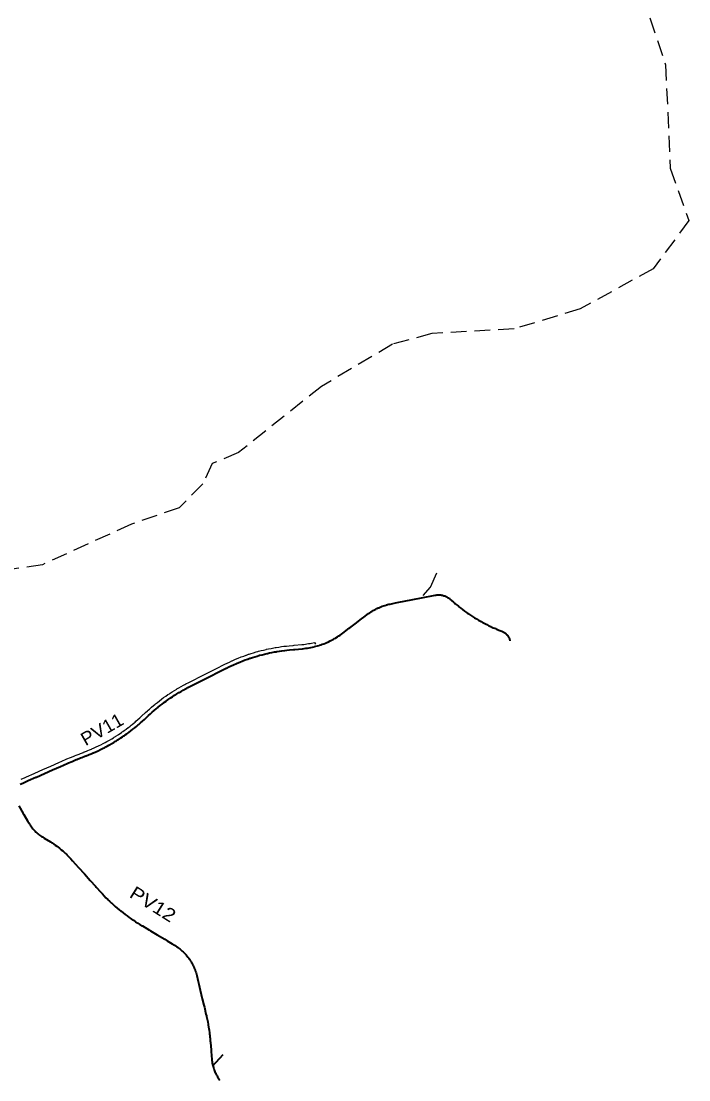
# Model space of a CAD drawing. Extents: x -509392 to -507242, y -1124532 to -1120864.
# Drawn here: x -508000 to -507242, y -1123169 to -1121966 of the extents above; entities that cross this region are included whole.
import ezdxf
from ezdxf.enums import TextEntityAlignment as Align

# ---------------------------------------------------------------- set-up
doc = ezdxf.new("R2010")
doc.units = 0
doc.header["$LTSCALE"] = 6
doc.linetypes.add('DOT_DASHED', pattern=[7.7, 5, -1.2, 0.3, -1.2])
doc.linetypes.add('MEDIUM_DASHED', pattern=[4.5, 3, -1.5])
for name, color, linetype, lineweight in [('1', 7, 'DOT_DASHED', 25), ('15', 7, 'Continuous', 35), ('3', 7, 'MEDIUM_DASHED', 25)]:
    doc.layers.add(name, color=color, linetype=linetype, lineweight=lineweight)

msp = doc.modelspace()

# ---------------------------------------------------------------- linework, layer by layer
at = {"layer": '1'}
for points in [[(-507856.144, -1122748.853), (-507854.55, -1122747.419), (-507852.329, -1122745.473), (-507850.08, -1122743.557), (-507848.408, -1122742.17), (-507847.798, -1122741.67), (-507845.497, -1122739.822), (-507843.165, -1122738.006), (-507840.813, -1122736.226), (-507840.332, -1122735.869), (-507838.425, -1122734.472), (-507836.018, -1122732.759), (-507833.588, -1122731.08), (-507831.962, -1122729.987), (-507831.127, -1122729.433), (-507828.651, -1122727.826), (-507826.149, -1122726.254), (-507823.629, -1122724.722), (-507823.297, -1122724.523), (-507821.077, -1122723.218), (-507818.509, -1122721.755), (-507815.922, -1122720.331), (-507814.381, -1122719.506), (-507813.312, -1122718.942), (-507812.782, -1122718.667), (-507812.454, -1122718.496), (-507810.686, -1122717.594), (-507805.385, -1122714.919), (-507796.457, -1122710.415), (-507787.529, -1122705.911), (-507778.601, -1122701.407), (-507769.672, -1122696.902), (-507769.044, -1122696.586), (-507766.414, -1122695.283), (-507763.758, -1122694.014), (-507761.089, -1122692.786), (-507760.447, -1122692.497), (-507758.394, -1122691.592), (-507756.813, -1122690.912), (-507755.681, -1122690.437), (-507752.963, -1122689.325), (-507751.008, -1122688.554), (-507750.216, -1122688.248), (-507747.465, -1122687.214), (-507744.701, -1122686.221), (-507744.461, -1122686.137), (-507741.916, -1122685.264), (-507741.369, -1122685.082), (-507739.113, -1122684.347), (-507736.304, -1122683.472), (-507733.484, -1122682.639), (-507731.585, -1122682.102), (-507730.644, -1122681.842), (-507727.802, -1122681.09), (-507724.947, -1122680.378), (-507722.088, -1122679.709), (-507721.649, -1122679.61), (-507719.205, -1122679.077), (-507716.322, -1122678.489), (-507713.432, -1122677.942), (-507711.614, -1122677.62), (-507710.526, -1122677.436), (-507707.624, -1122676.973), (-507704.71, -1122676.551), (-507701.806, -1122676.173)], [(-507701.789, -1122676.171), (-507701.477, -1122676.133), (-507698.867, -1122675.833), (-507695.947, -1122675.538), (-507691.407, -1122675.113), (-507690.016, -1122674.982), (-507681.451, -1122674.179), (-507681.066, -1122674.143), (-507679.254, -1122673.954), (-507677.456, -1122673.727), (-507675.664, -1122673.463), (-507673.878, -1122673.16), (-507672.096, -1122672.819), (-507672.079, -1122672.815), (-507670.328, -1122672.442), (-507667.071, -1122671.673), (-507665.943, -1122673.704)], [(-508000.267, -1122827.114), (-507995.799, -1122825.113), (-507994.074, -1122824.35), (-507985.697, -1122820.648), (-507984.928, -1122820.308), (-507975.78, -1122816.265), (-507966.634, -1122812.223), (-507957.487, -1122808.18), (-507954.038, -1122806.656), (-507949.198, -1122804.547), (-507948.269, -1122804.149), (-507944.323, -1122802.483), (-507939.437, -1122800.475), (-507938.945, -1122800.276), (-507934.523, -1122798.515), (-507933.03, -1122797.931), (-507929.589, -1122796.606), (-507929.549, -1122796.591), (-507928.434, -1122796.167), (-507928.019, -1122796.009), (-507925.363, -1122794.975), (-507924.69, -1122794.707), (-507922.741, -1122793.911), (-507920.449, -1122792.944), (-507920.133, -1122792.808), (-507917.531, -1122791.663), (-507914.952, -1122790.482), (-507912.385, -1122789.263), (-507911.585, -1122788.873), (-507909.847, -1122788.012), (-507907.316, -1122786.717), (-507906.364, -1122786.218), (-507904.814, -1122785.391), (-507902.923, -1122784.358), (-507902.332, -1122784.029), (-507899.86, -1122782.626), (-507897.413, -1122781.19), (-507895.497, -1122780.032), (-507894.989, -1122779.719), (-507894.509, -1122779.422), (-507892.956, -1122778.448), (-507892.591, -1122778.216), (-507890.199, -1122776.668), (-507889.58, -1122776.259), (-507887.845, -1122775.095), (-507886.344, -1122774.065), (-507885.509, -1122773.485), (-507884.746, -1122772.949), (-507883.2, -1122771.844), (-507880.91, -1122770.165), (-507878.642, -1122768.451), (-507878.465, -1122768.315), (-507876.407, -1122766.71), (-507875.291, -1122765.823), (-507874.199, -1122764.94), (-507872.008, -1122763.129), (-507870.874, -1122762.169), (-507869.852, -1122761.294), (-507867.716, -1122759.422), (-507865.606, -1122757.516), (-507863.541, -1122755.625), (-507858.982, -1122751.45), (-507858.951, -1122751.421), (-507856.743, -1122749.4), (-507856.153, -1122748.862)]]:
    msp.add_lwpolyline(points, dxfattribs=at)
at = {"layer": '15'}
msp.add_line((-507782.865, -1123153.213), (-507770.728, -1123139.816), dxfattribs=at)
for points in [[(-507585.778, -1122629.265), (-507584.798, -1122628.997), (-507584.242, -1122628.854), (-507582.695, -1122628.483), (-507581.139, -1122628.154), (-507575.013, -1122626.942), (-507571.329, -1122626.213), (-507565.204, -1122625.002), (-507555.394, -1122623.061), (-507545.584, -1122621.121), (-507539.977, -1122620.012), (-507535.774, -1122619.18), (-507533.733, -1122618.776), (-507530.167, -1122618.071), (-507529.251, -1122617.912), (-507528.329, -1122617.796), (-507527.402, -1122617.722), (-507526.473, -1122617.692), (-507525.907, -1122617.695), (-507525.544, -1122617.705), (-507524.616, -1122617.761), (-507524.374, -1122617.782), (-507523.691, -1122617.86), (-507522.773, -1122618.002), (-507521.862, -1122618.186), (-507520.96, -1122618.413), (-507520.07, -1122618.681), (-507519.194, -1122618.991), (-507518.332, -1122619.34), (-507517.488, -1122619.73), (-507516.663, -1122620.158), (-507516.367, -1122620.324), (-507515.859, -1122620.624), (-507515.077, -1122621.127), (-507514.32, -1122621.666), (-507513.588, -1122622.239), (-507512.884, -1122622.846), (-507511.688, -1122623.925), (-507511.332, -1122624.247), (-507509.316, -1122626.039), (-507508.635, -1122626.633), (-507508.23, -1122626.983), (-507507.274, -1122627.801), (-507505.205, -1122629.533), (-507503.721, -1122630.743), (-507503.111, -1122631.233), (-507500.992, -1122632.902), (-507500.902, -1122632.971), (-507498.847, -1122634.538), (-507496.679, -1122636.142), (-507494.487, -1122637.714), (-507492.829, -1122638.87), (-507492.271, -1122639.253), (-507490.033, -1122640.758), (-507487.772, -1122642.229), (-507485.489, -1122643.667), (-507484.441, -1122644.312), (-507483.186, -1122645.07), (-507480.861, -1122646.438), (-507478.516, -1122647.772), (-507477.876, -1122648.128), (-507476.152, -1122649.07), (-507475.763, -1122649.279), (-507473.768, -1122650.333), (-507471.366, -1122651.559)], [(-507701.213, -1122680.886), (-507700.912, -1122680.849), (-507698.357, -1122680.556), (-507695.496, -1122680.267), (-507690.964, -1122679.842), (-507689.573, -1122679.711), (-507681.007, -1122678.908), (-507680.612, -1122678.871), (-507678.71, -1122678.673), (-507676.812, -1122678.433), (-507674.92, -1122678.154), (-507673.035, -1122677.835), (-507671.157, -1122677.475), (-507671.117, -1122677.467), (-507669.286, -1122677.076), (-507667.425, -1122676.637), (-507667.216, -1122676.585), (-507665.573, -1122676.158), (-507663.732, -1122675.641), (-507661.903, -1122675.084), (-507661.447, -1122674.939), (-507660.085, -1122674.489), (-507658.281, -1122673.855), (-507656.491, -1122673.183), (-507654.715, -1122672.473), (-507652.955, -1122671.725), (-507652.117, -1122671.354), (-507651.211, -1122670.94), (-507649.484, -1122670.119), (-507647.775, -1122669.261), (-507646.084, -1122668.366), (-507645.681, -1122668.146), (-507644.413, -1122667.436), (-507643.242, -1122666.757), (-507642.762, -1122666.471), (-507641.132, -1122665.471), (-507639.524, -1122664.436), (-507637.938, -1122663.368), (-507636.375, -1122662.266), (-507634.932, -1122661.204), (-507634.836, -1122661.131), (-507627.649, -1122655.713), (-507626.947, -1122655.184), (-507619.447, -1122649.53), (-507618.962, -1122649.164), (-507613.599, -1122645.122), (-507610.976, -1122643.145), (-507605.614, -1122639.102), (-507604.331, -1122638.162), (-507603.024, -1122637.255), (-507602.938, -1122637.198), (-507601.693, -1122636.384), (-507600.34, -1122635.548), (-507598.965, -1122634.749), (-507597.569, -1122633.986), (-507596.154, -1122633.261), (-507594.72, -1122632.573), (-507594.211, -1122632.34), (-507593.268, -1122631.923), (-507591.799, -1122631.313), (-507590.315, -1122630.741), (-507588.816, -1122630.209), (-507587.303, -1122629.717), (-507586.14, -1122629.368), (-507585.778, -1122629.265)], [(-507471.366, -1122651.559), (-507468.945, -1122652.75), (-507466.823, -1122653.757), (-507466.507, -1122653.904), (-507464.052, -1122655.022), (-507462.37, -1122655.762), (-507461.58, -1122656.102), (-507460.262, -1122656.661), (-507459.093, -1122657.146), (-507457.648, -1122657.732), (-507456.59, -1122658.152), (-507454.322, -1122659.044), (-507453.594, -1122659.352), (-507452.884, -1122659.699), (-507452.192, -1122660.082), (-507451.522, -1122660.502), (-507450.875, -1122660.956), (-507450.253, -1122661.444), (-507449.657, -1122661.963), (-507449.089, -1122662.514), (-507449.02, -1122662.585), (-507448.551, -1122663.093), (-507448.045, -1122663.701), (-507447.571, -1122664.334), (-507447.131, -1122664.991), (-507446.727, -1122665.67), (-507446.359, -1122666.37), (-507446.157, -1122666.795), (-507446.028, -1122667.088), (-507445.753, -1122667.773), (-507445.735, -1122667.822), (-507445.482, -1122668.571), (-507445.268, -1122669.332), (-507445.14, -1122669.84)], [(-507852.957, -1122752.376), (-507851.394, -1122750.97), (-507849.223, -1122749.067), (-507847.025, -1122747.195), (-507845.391, -1122745.838), (-507844.8, -1122745.355), (-507842.549, -1122743.548), (-507840.272, -1122741.773), (-507837.97, -1122740.031), (-507837.508, -1122739.687), (-507835.643, -1122738.323), (-507833.291, -1122736.648), (-507830.916, -1122735.007), (-507829.327, -1122733.938), (-507828.517, -1122733.401), (-507826.095, -1122731.83), (-507823.65, -1122730.294), (-507821.184, -1122728.793), (-507820.869, -1122728.605), (-507818.696, -1122727.328), (-507816.188, -1122725.9), (-507813.659, -1122724.507), (-507812.155, -1122723.701), (-507811.11, -1122723.151), (-507810.592, -1122722.882), (-507810.275, -1122722.717), (-507808.542, -1122721.832), (-507803.246, -1122719.16), (-507794.318, -1122714.656), (-507785.389, -1122710.152), (-507776.461, -1122705.648), (-507767.533, -1122701.144), (-507766.912, -1122700.83), (-507764.335, -1122699.554), (-507761.741, -1122698.314), (-507759.13, -1122697.112), (-507758.51, -1122696.834), (-507756.501, -1122695.948), (-507754.955, -1122695.285), (-507753.856, -1122694.822), (-507751.194, -1122693.734), (-507749.284, -1122692.98), (-507748.518, -1122692.684), (-507745.827, -1122691.673), (-507743.121, -1122690.7), (-507742.899, -1122690.622), (-507740.402, -1122689.767), (-507739.877, -1122689.592), (-507737.669, -1122688.872), (-507734.924, -1122688.018), (-507732.168, -1122687.202), (-507730.312, -1122686.678), (-507729.399, -1122686.427), (-507726.62, -1122685.691), (-507723.83, -1122684.995), (-507721.031, -1122684.34), (-507720.613, -1122684.245), (-507718.223, -1122683.724), (-507715.406, -1122683.149), (-507712.581, -1122682.615), (-507710.805, -1122682.301), (-507709.748, -1122682.122), (-507706.909, -1122681.669), (-507704.064, -1122681.257), (-507701.213, -1122680.886)], [(-507998.313, -1122831.443), (-507993.874, -1122829.455), (-507992.153, -1122828.695), (-507983.776, -1122824.992), (-507983.007, -1122824.652), (-507973.86, -1122820.61), (-507964.714, -1122816.567), (-507955.568, -1122812.525), (-507952.123, -1122811.002), (-507947.32, -1122808.909), (-507946.405, -1122808.518), (-507942.495, -1122806.867), (-507937.65, -1122804.876), (-507937.171, -1122804.682), (-507932.784, -1122802.935), (-507931.31, -1122802.359), (-507927.898, -1122801.045), (-507927.861, -1122801.031), (-507926.744, -1122800.606), (-507926.321, -1122800.445), (-507923.613, -1122799.392), (-507922.916, -1122799.113), (-507920.921, -1122798.299), (-507918.58, -1122797.311), (-507918.245, -1122797.167), (-507915.586, -1122795.997), (-507912.944, -1122794.788), (-507910.319, -1122793.54), (-507909.493, -1122793.138), (-507907.714, -1122792.255), (-507905.127, -1122790.932), (-507904.145, -1122790.418), (-507902.559, -1122789.572), (-507900.627, -1122788.516), (-507900.012, -1122788.174), (-507897.485, -1122786.74), (-507894.979, -1122785.269), (-507893.019, -1122784.084), (-507892.495, -1122783.762), (-507892.002, -1122783.457), (-507890.416, -1122782.462), (-507890.033, -1122782.219), (-507887.594, -1122780.64), (-507886.953, -1122780.216), (-507885.178, -1122779.026), (-507883.641, -1122777.972), (-507882.786, -1122777.377), (-507882.003, -1122776.826), (-507880.418, -1122775.693), (-507878.074, -1122773.976), (-507875.756, -1122772.224), (-507875.565, -1122772.077), (-507873.463, -1122770.439), (-507872.319, -1122769.528), (-507871.197, -1122768.621), (-507868.957, -1122766.77), (-507867.793, -1122765.786), (-507866.745, -1122764.886), (-507864.56, -1122762.971), (-507862.403, -1122761.024), (-507860.333, -1122759.128), (-507855.766, -1122754.946), (-507855.734, -1122754.917), (-507853.537, -1122752.904), (-507852.957, -1122752.376)], [(-508001.273, -1122832.797), (-507998.313, -1122831.443)], [(-508002.892, -1122857.242), (-507997.895, -1122865.904), (-507997.186, -1122867.133), (-507992.898, -1122874.567), (-507992.519, -1122875.225), (-507991.583, -1122876.847), (-507990.892, -1122878.006), (-507990.186, -1122879.113), (-507989.449, -1122880.2), (-507988.681, -1122881.263), (-507987.868, -1122882.322), (-507987.052, -1122883.323), (-507986.193, -1122884.316), (-507985.304, -1122885.285), (-507984.389, -1122886.228), (-507983.447, -1122887.142), (-507982.476, -1122888.031), (-507981.589, -1122888.798), (-507981.51, -1122888.864), (-507980.465, -1122889.715), (-507979.423, -1122890.513), (-507978.358, -1122891.28), (-507977.271, -1122892.016), (-507976.132, -1122892.74), (-507974.011, -1122894.045), (-507966.909, -1122898.413), (-507966.748, -1122898.513), (-507966.549, -1122898.637), (-507965.442, -1122899.334), (-507965.083, -1122899.563), (-507963.303, -1122900.735), (-507961.535, -1122901.952), (-507959.79, -1122903.205), (-507958.077, -1122904.49), (-507956.884, -1122905.418), (-507956.366, -1122905.83), (-507954.716, -1122907.176), (-507953.079, -1122908.569), (-507951.472, -1122909.993), (-507949.902, -1122911.443), (-507948.976, -1122912.327), (-507948.336, -1122912.951), (-507946.829, -1122914.461), (-507945.357, -1122916), (-507944.93, -1122916.458), (-507943.903, -1122917.582), (-507941.864, -1122919.847), (-507935.174, -1122927.279), (-507928.485, -1122934.711), (-507921.794, -1122942.143), (-507915.899, -1122948.692), (-507915.104, -1122949.575), (-507909.886, -1122955.372), (-507908.436, -1122956.966), (-507907.937, -1122957.505), (-507905.946, -1122959.621), (-507903.934, -1122961.696), (-507901.881, -1122963.752), (-507901.674, -1122963.955), (-507899.819, -1122965.756), (-507897.688, -1122967.765)], [(-507897.741, -1122967.716), (-507895.575, -1122969.7), (-507894.543, -1122970.625), (-507893.43, -1122971.608), (-507891.232, -1122973.503), (-507889.014, -1122975.361), (-507887.091, -1122976.926), (-507886.786, -1122977.17), (-507884.501, -1122978.972), (-507882.205, -1122980.727), (-507879.872, -1122982.456), (-507879.357, -1122982.829), (-507877.528, -1122984.139), (-507876.604, -1122984.788), (-507875.167, -1122985.783), (-507872.758, -1122987.406), (-507871.309, -1122988.359), (-507870.352, -1122988.978), (-507867.899, -1122990.528), (-507865.417, -1122992.046), (-507862.963, -1122993.521), (-507862.498, -1122993.8), (-507857.72, -1122996.674), (-507854.389, -1122998.676), (-507853.211, -1122999.385), (-507845.82, -1123003.828), (-507837.249, -1123008.982), (-507834.562, -1123010.599), (-507828.68, -1123014.136), (-507825.963, -1123015.769), (-507824.667, -1123016.574), (-507823.365, -1123017.434), (-507822.088, -1123018.331), (-507820.841, -1123019.26), (-507819.829, -1123020.057), (-507819.591, -1123020.25), (-507818.426, -1123021.226), (-507817.621, -1123021.934), (-507817.231, -1123022.286), (-507816.112, -1123023.338), (-507815.006, -1123024.438), (-507813.931, -1123025.57), (-507812.892, -1123026.728), (-507812.013, -1123027.761), (-507811.863, -1123027.941), (-507810.905, -1123029.139), (-507809.965, -1123030.385), (-507809.062, -1123031.656), (-507808.194, -1123032.953), (-507807.364, -1123034.273), (-507806.637, -1123035.503), (-507806.568, -1123035.622), (-507805.868, -1123036.887), (-507805.793, -1123037.029), (-507805.101, -1123038.37), (-507804.425, -1123039.776), (-507803.789, -1123041.203), (-507803.195, -1123042.644), (-507802.641, -1123044.102), (-507802.129, -1123045.577), (-507801.66, -1123047.063), (-507801.636, -1123047.149), (-507801.232, -1123048.565), (-507800.855, -1123050.044), (-507799.183, -1123057.026)], [(-507799.183, -1123057.028), (-507798.858, -1123058.385), (-507798.518, -1123059.802), (-507796.854, -1123066.751), (-507794.526, -1123076.476), (-507792.745, -1123083.911), (-507792.197, -1123086.201), (-507790.374, -1123093.813), (-507789.869, -1123095.975), (-507789.678, -1123096.823), (-507789.029, -1123099.829), (-507788.423, -1123102.859), (-507787.868, -1123105.872), (-507787.839, -1123106.037), (-507787.351, -1123108.934), (-507787.115, -1123110.433), (-507786.879, -1123112.006), (-507786.46, -1123115.047), (-507786.317, -1123116.169), (-507786.082, -1123118.127), (-507785.811, -1123120.625), (-507785.752, -1123121.213), (-507785.471, -1123124.254), (-507785.297, -1123126.311), (-507784.614, -1123134.388), (-507784.455, -1123136.276), (-507783.669, -1123145.579), (-507783.615, -1123146.17), (-507783.538, -1123146.903), (-507783.45, -1123147.62), (-507783.373, -1123148.184), (-507783.164, -1123149.497), (-507782.921, -1123150.789), (-507782.641, -1123152.07), (-507782.323, -1123153.342), (-507781.962, -1123154.628), (-507781.858, -1123154.972), (-507781.581, -1123155.846), (-507781.15, -1123157.097), (-507780.686, -1123158.323), (-507780.187, -1123159.536), (-507779.652, -1123160.734), (-507779.083, -1123161.916), (-507778.464, -1123163.111), (-507778.389, -1123163.252), (-507777.846, -1123164.221), (-507777.173, -1123165.355), (-507776.471, -1123166.463), (-507775.736, -1123167.55), (-507775.002, -1123168.571), (-507775.074, -1123168.48)]]:
    msp.add_lwpolyline(points, dxfattribs=at)
at = {"layer": '3'}
for points in [[(-507286.361, -1121962.404), (-507268.347, -1122015.595), (-507263.03, -1122133.19), (-507241.929, -1122192.653), (-507282.455, -1122247.442), (-507365.39, -1122293.005), (-507440.451, -1122315.723), (-507533.877, -1122321.034), (-507578.697, -1122333.173), (-507659.214, -1122380.969), (-507753.404, -1122456.078), (-507783.433, -1122468.728), (-507794.067, -1122491.488), (-507820.653, -1122518.8), (-507875.139, -1122537.55), (-507976.136, -1122583.478), (-508041.695, -1122593.151), (-508117.175, -1122582.596), (-508239.141, -1122537.589), (-508323.505, -1122486.177), (-508363.004, -1122411.827), (-508365.999, -1122368.448), (-508389.751, -1122354.254)], [(-507543.526, -1122618.421), (-507535.337, -1122609.137), (-507527.149, -1122590.025)]]:
    msp.add_lwpolyline(points, dxfattribs=at)

# ---------------------------------------------------------------- texts
at = {"layer": '1'}
for s, rotation, width, p in [('PV11', 29.753, 1.05, (-507904.771, -1122776.939)), ('PV12', 327.816, 1.15, (-507854.605, -1122975.4))]:
    msp.add_text(s, height=15, rotation=rotation, dxfattribs=dict(at, width=width)).set_placement(p, align=Align.CENTER)

doc.saveas('drawing.dxf')
